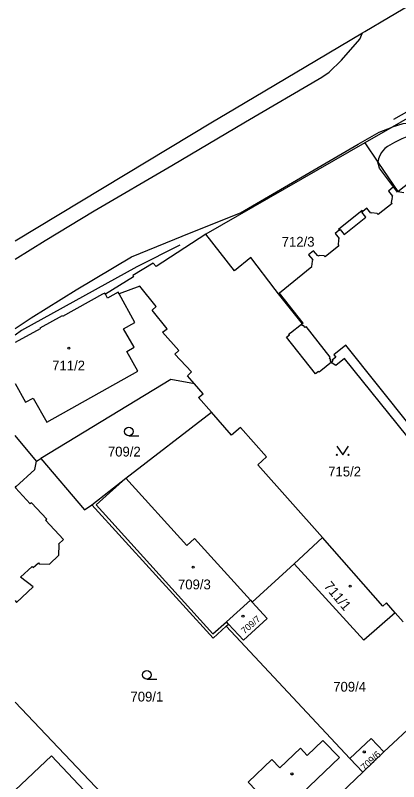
# Model space of a CAD drawing. Extents: x -496682 to -495776, y -1088797 to -1088018.
# Drawn here: x -496674.2 to -496607.7, y -1088218.9 to -1088086.1 of the extents above; entities that cross this region are included whole.
import ezdxf

# ---------------------------------------------------------------- set-up
doc = ezdxf.new("R2010")
doc.units = 0
for name, color, linetype in [('Hranice parcel', 7, 'Continuous'), ('Parcelní čísla', 7, 'Continuous'), ('Vnitřní kresba', 7, 'Continuous'), ('Značky budov', 7, 'Continuous'), ('Značky kultur', 7, 'Continuous')]:
    doc.layers.add(name, color=color, linetype=linetype)

msp = doc.modelspace()

# ---------------------------------------------------------------- linework, layer by layer
at = {"layer": 'Hranice parcel'}
for p, q in [((-496621.98, -1088093.87), (-496613.99, -1088089.14)), ((-496636.23, -1088102.32), (-496621.98, -1088093.87)), ((-496640.02, -1088104.57), (-496636.23, -1088102.32)), ((-496674.2, -1088125.19), (-496640.02, -1088104.57)), ((-496608.89, -1088105.48), (-496613.63, -1088108.21)), ((-496613.63, -1088108.21), (-496641.19, -1088124.04)), ((-496613.63, -1088108.21), (-496611.33, -1088111.59)), ((-496611.33, -1088111.59), (-496607.87, -1088116.66)), ((-496670.53, -1088163.38), (-496674.2, -1088158.91)), ((-496670.53, -1088163.38), (-496669.8, -1088162.94)), ((-496625.88, -1088181.17), (-496620.92, -1088176.62)), ((-496633.12, -1088187.81), (-496625.88, -1088181.17)), ((-496608.33, -1088189.64), (-496609.85, -1088187.91)), ((-496606.96, -1088191.2), (-496608.33, -1088189.64)), ((-496637.64, -1088191.96), (-496637.25, -1088191.6)), ((-496616.2, -1088214.91), (-496637.64, -1088191.96)), ((-496600.11, -1088204.23), (-496610.33, -1088213.73)), ((-496658.12, -1088222.07), (-496674.2, -1088205.13)), ((-496613.98, -1088217.23), (-496610.33, -1088213.73)), ((-496616.2, -1088214.91), (-496613.98, -1088217.23)), ((-496613.98, -1088217.23), (-496639.51, -1088241.62))]:
    msp.add_line(p, q, dxfattribs=at)
for points in [[(-496609.51, -1088086.48), (-496605.72, -1088084.28), (-496593.73, -1088076.81)], [(-496613.99, -1088089.14), (-496613.61, -1088088.91), (-496609.51, -1088086.48)], [(-496674.2, -1088128.35), (-496669.03, -1088125.12), (-496660.52, -1088120.02), (-496647.07, -1088112.13), (-496634.28, -1088104.6), (-496621.09, -1088096.86), (-496619.81, -1088095.95), (-496617.66, -1088093.89), (-496614.48, -1088090.27), (-496613.99, -1088089.14)], [(-496598.59, -1088099.57), (-496601.77, -1088101.39), (-496608.89, -1088105.48)], [(-496591.05, -1088108.96), (-496593.52, -1088107.29), (-496597.24, -1088105.41), (-496601.51, -1088104.53), (-496607, -1088104.91), (-496608.89, -1088105.48)], [(-496674.2, -1088140.36), (-496671.45, -1088138.52), (-496663.66, -1088133.7), (-496654.08, -1088127.99), (-496643.7, -1088123.78), (-496635.19, -1088120.33), (-496614.78, -1088108.46), (-496611.14, -1088106.36), (-496608.89, -1088105.48)], [(-496598.83, -1088108.3), (-496599.53, -1088107.78), (-496600.29, -1088107.35), (-496601.08, -1088107.01), (-496601.29, -1088106.94), (-496602.12, -1088106.72), (-496602.98, -1088106.59), (-496603.85, -1088106.57), (-496604.72, -1088106.64), (-496606.05, -1088107.08), (-496607.21, -1088107.55), (-496608.47, -1088108.16), (-496609.68, -1088108.86), (-496610.16, -1088109.22), (-496610.57, -1088109.66), (-496610.74, -1088109.91), (-496611.03, -1088110.43), (-496611.23, -1088111), (-496611.33, -1088111.59)], [(-496607.87, -1088116.66), (-496601, -1088111.2), (-496591.02, -1088123.77), (-496593.66, -1088125.97), (-496582.54, -1088140.01), (-496605.81, -1088158.61), (-496606.3, -1088159)], [(-496607.87, -1088116.66), (-496607.94, -1088116.74), (-496608.64, -1088115.87), (-496609.51, -1088116.57), (-496608.81, -1088117.44), (-496608.91, -1088117.51), (-496608.81, -1088117.63), (-496608.89, -1088117.7), (-496609.04, -1088118.55), (-496608.88, -1088118.74), (-496611.31, -1088120.66), (-496611.46, -1088120.47), (-496612.48, -1088120.33), (-496612.57, -1088120.4), (-496613.26, -1088119.54), (-496613.96, -1088120.1), (-496614.09, -1088119.93), (-496618.2, -1088123.21), (-496618.07, -1088123.38), (-496618.77, -1088123.93), (-496618.07, -1088124.8), (-496618.19, -1088124.89), (-496618.1, -1088125.01), (-496618.18, -1088125.07), (-496618.25, -1088125.89), (-496618.09, -1088126.08), (-496620.51, -1088128), (-496620.67, -1088127.81), (-496621.51, -1088127.73), (-496621.59, -1088127.83), (-496621.69, -1088127.72), (-496621.78, -1088127.8), (-496622.48, -1088126.93), (-496623.35, -1088127.62), (-496622.65, -1088128.49), (-496622.75, -1088128.57), (-496622.66, -1088128.69), (-496622.73, -1088128.75), (-496622.86, -1088129.62), (-496622.78, -1088129.72), (-496628.4, -1088134.25), (-496628.56, -1088134.37)], [(-496641.19, -1088124.04), (-496649.8, -1088129.65), (-496650.32, -1088129.05), (-496653.81, -1088131.22), (-496653.69, -1088131.42), (-496658.59, -1088134.42)], [(-496628.56, -1088134.37), (-496629.13, -1088133.65), (-496633.36, -1088128.1), (-496636.22, -1088130.38), (-496641.19, -1088124.04)], [(-496643.14, -1088149.97), (-496644.35, -1088148.57), (-496643.66, -1088147.87), (-496646.57, -1088144.85), (-496645.87, -1088144.18), (-496648.66, -1088141.04), (-496647.86, -1088140.46), (-496650.49, -1088137.24), (-496649.78, -1088136.55), (-496652.62, -1088133.08), (-496656.21, -1088134.37), (-496656.38, -1088134.07), (-496658.2, -1088135.12), (-496658.59, -1088134.42)], [(-496658.59, -1088134.42), (-496658.69, -1088134.24), (-496659.06, -1088134.44), (-496666.03, -1088138.3), (-496666.08, -1088138.21), (-496669.97, -1088140.33), (-496669.9, -1088140.44), (-496674.2, -1088142.82)], [(-496606.3, -1088159), (-496617.15, -1088145.59), (-496618.65, -1088146.8), (-496619.26, -1088146.37), (-496619.37, -1088146.24), (-496621.25, -1088147.74), (-496621.51, -1088147.95), (-496621.62, -1088147.82), (-496622.15, -1088148.24), (-496627.2, -1088141.89), (-496626.66, -1088141.46), (-496626.77, -1088141.33), (-496626.5, -1088141.12), (-496624.56, -1088139.66), (-496624.44, -1088139.56), (-496628.56, -1088134.37)], [(-496643.14, -1088149.97), (-496647.25, -1088149.22), (-496669.8, -1088162.94)], [(-496640.19, -1088154.91), (-496642.46, -1088152.32), (-496641.63, -1088151.71), (-496643.14, -1088149.97)], [(-496660.95, -1088170.93), (-496655.03, -1088166.3), (-496640.19, -1088154.91)], [(-496620.92, -1088176.62), (-496632.18, -1088164.01), (-496630.65, -1088162.63), (-496635.17, -1088157.53), (-496636.71, -1088158.87), (-496640.19, -1088154.91)], [(-496674.2, -1088187.5), (-496673.99, -1088187.86), (-496671.11, -1088185.12), (-496673.29, -1088183.5), (-496671.29, -1088181.61), (-496671.08, -1088181.82), (-496670.21, -1088181), (-496670.09, -1088181.16), (-496668.29, -1088181.2), (-496666.68, -1088179.68), (-496666.6, -1088177.86), (-496666.74, -1088177.74), (-496665.86, -1088176.92), (-496668.94, -1088173.62), (-496668.73, -1088173.43), (-496671.4, -1088170.57), (-496671.61, -1088170.77), (-496674.19, -1088168.01), (-496674.09, -1088167.82), (-496670.82, -1088164.79), (-496670.53, -1088163.38)], [(-496669.8, -1088162.94), (-496662.21, -1088171.82), (-496660.95, -1088170.93)], [(-496660.95, -1088170.93), (-496639.93, -1088194.06), (-496637.64, -1088191.96)], [(-496609.85, -1088187.91), (-496610.48, -1088188.52), (-496620.92, -1088176.62)], [(-496608.33, -1088189.64), (-496613.76, -1088194.39), (-496625.88, -1088181.17)], [(-496637.25, -1088191.6), (-496637.61, -1088191.2), (-496633.42, -1088187.48), (-496633.12, -1088187.81)], [(-496637.25, -1088191.6), (-496634.67, -1088194.4), (-496630.55, -1088190.63), (-496633.12, -1088187.81)], [(-496610.33, -1088213.73), (-496612.51, -1088211.45), (-496616.2, -1088214.91)], [(-496624.78, -1088213.12), (-496628.32, -1088216.5), (-496629.71, -1088215.04), (-496633.83, -1088218.99), (-496628.4, -1088224.66), (-496618, -1088214.72), (-496620.89, -1088211.75), (-496623.61, -1088214.35), (-496624.78, -1088213.12)], [(-496659.48, -1088223.35), (-496667.9, -1088214.43), (-496674.2, -1088220.39)]]:
    msp.add_lwpolyline(points, dxfattribs=at)
at = {"layer": 'Vnitřní kresba'}
for p, q in [((-496611.04, -1088112.6), (-496611.33, -1088111.59)), ((-496608.64, -1088115.87), (-496611.04, -1088112.6)), ((-496607.87, -1088116.66), (-496606.83, -1088116.82)), ((-496617.21, -1088124.11), (-496613.44, -1088121.09)), ((-496614.13, -1088120.23), (-496613.96, -1088120.1)), ((-496613.44, -1088121.09), (-496614.13, -1088120.23)), ((-496618.07, -1088123.38), (-496617.9, -1088123.24)), ((-496617.9, -1088123.24), (-496617.21, -1088124.11)), ((-496653.46, -1088139.37), (-496656.21, -1088134.37)), ((-496624.29, -1088139.44), (-496628.4, -1088134.25)), ((-496655.42, -1088140.45), (-496653.46, -1088139.37)), ((-496624.34, -1088139.94), (-496624.56, -1088139.66)), ((-496624.44, -1088139.56), (-496624.29, -1088139.44)), ((-496653.59, -1088143.63), (-496655.42, -1088140.45)), ((-496624.22, -1088139.84), (-496624.34, -1088139.94)), ((-496623.94, -1088140.19), (-496624.22, -1088139.84)), ((-496623.79, -1088140.07), (-496623.94, -1088140.19)), ((-496619.61, -1088145.35), (-496623.79, -1088140.07)), ((-496654.89, -1088144.39), (-496653.59, -1088143.63)), ((-496616.9, -1088143.28), (-496618.98, -1088144.95)), ((-496605.68, -1088157.3), (-496616.9, -1088143.28)), ((-496652.96, -1088147.79), (-496654.89, -1088144.39)), ((-496618.98, -1088144.95), (-496618.65, -1088145.37)), ((-496619.76, -1088145.46), (-496619.61, -1088145.35)), ((-496619.48, -1088145.81), (-496619.76, -1088145.46)), ((-496619.6, -1088145.91), (-496619.48, -1088145.81)), ((-496619.37, -1088146.24), (-496619.6, -1088145.91)), ((-496619.18, -1088145.96), (-496619.37, -1088146.24)), ((-496618.65, -1088145.37), (-496619.26, -1088145.86)), ((-496619.26, -1088145.86), (-496619.18, -1088145.96)), ((-496668.76, -1088156.6), (-496652.96, -1088147.79)), ((-496674.2, -1088149.91), (-496672.41, -1088153.15)), ((-496672.41, -1088153.15), (-496671.1, -1088152.43)), ((-496671.1, -1088152.43), (-496668.76, -1088156.6)), ((-496660.17, -1088170.95), (-496655.03, -1088166.3)), ((-496655.03, -1088166.3), (-496644.44, -1088178)), ((-496674.2, -1088167.71), (-496674.09, -1088167.82)), ((-496639.95, -1088193.27), (-496660.17, -1088170.95)), ((-496644.44, -1088178), (-496643.11, -1088176.8)), ((-496643.11, -1088176.8), (-496633.42, -1088187.48)), ((-496639.95, -1088193.27), (-496637.61, -1088191.2))]:
    msp.add_line(p, q, dxfattribs=at)
for points in [[(-496513.9, -1088047.1), (-496531.42, -1088056.78), (-496539.98, -1088064.95), (-496573.76, -1088084.47), (-496608.65, -1088104.15)], [(-496645.68, -1088125.97), (-496653.14, -1088129.7), (-496673.12, -1088140.73), (-496674.2, -1088141.52)]]:
    msp.add_lwpolyline(points, dxfattribs=at)
at = {"layer": 'Značky budov'}
for centre in [(-496664.93, -1088143.8), (-496643.38, -1088181.72), (-496616.16, -1088185.03), (-496634.73, -1088190.21), (-496613.7, -1088213.76), (-496626.24, -1088217.57)]:
    msp.add_circle(centre, 0.175, dxfattribs=at)
at = {"layer": 'Značky kultur'}
for p, q in [((-496654.54, -1088159), (-496652.79, -1088159)), ((-496651.39, -1088201.13), (-496649.64, -1088201.13))]:
    msp.add_line(p, q, dxfattribs=at)
msp.add_lwpolyline([(-496618.45, -1088160.77), (-496617.45, -1088162.27), (-496616.45, -1088160.77)], dxfattribs=at)
for centre, radius in [((-496654.54, -1088158.25), 0.75), ((-496618.45, -1088162.27), 0.1), ((-496616.45, -1088162.27), 0.1), ((-496651.39, -1088200.38), 0.75)]:
    msp.add_circle(centre, radius, dxfattribs=at)

# ---------------------------------------------------------------- texts
at = {"layer": 'Parcelní čísla'}
for s, p in [('712/3', (-496628.02, -1088126.21)), ('711/2', (-496667.81, -1088147.66)), ('709/2', (-496658.15, -1088162.57)), ('715/2', (-496619.96, -1088166.02)), ('709/3', (-496646, -1088185.58)), ('709/4', (-496619.09, -1088203.31)), ('709/1', (-496654.24, -1088205.02))]:
    msp.add_text(s, height=1.7, dxfattribs=at).set_placement(p)
for s, height, rotation, p in [('711/1', 1.7, 310, (-496620.8, -1088185.09)), ('709/7', 1.139, 41, (-496634.45, -1088193.39)), ('709/6', 1.2, 43, (-496613.65, -1088217.08))]:
    msp.add_text(s, height=height, rotation=rotation, dxfattribs=at).set_placement(p)

doc.saveas('drawing.dxf')
